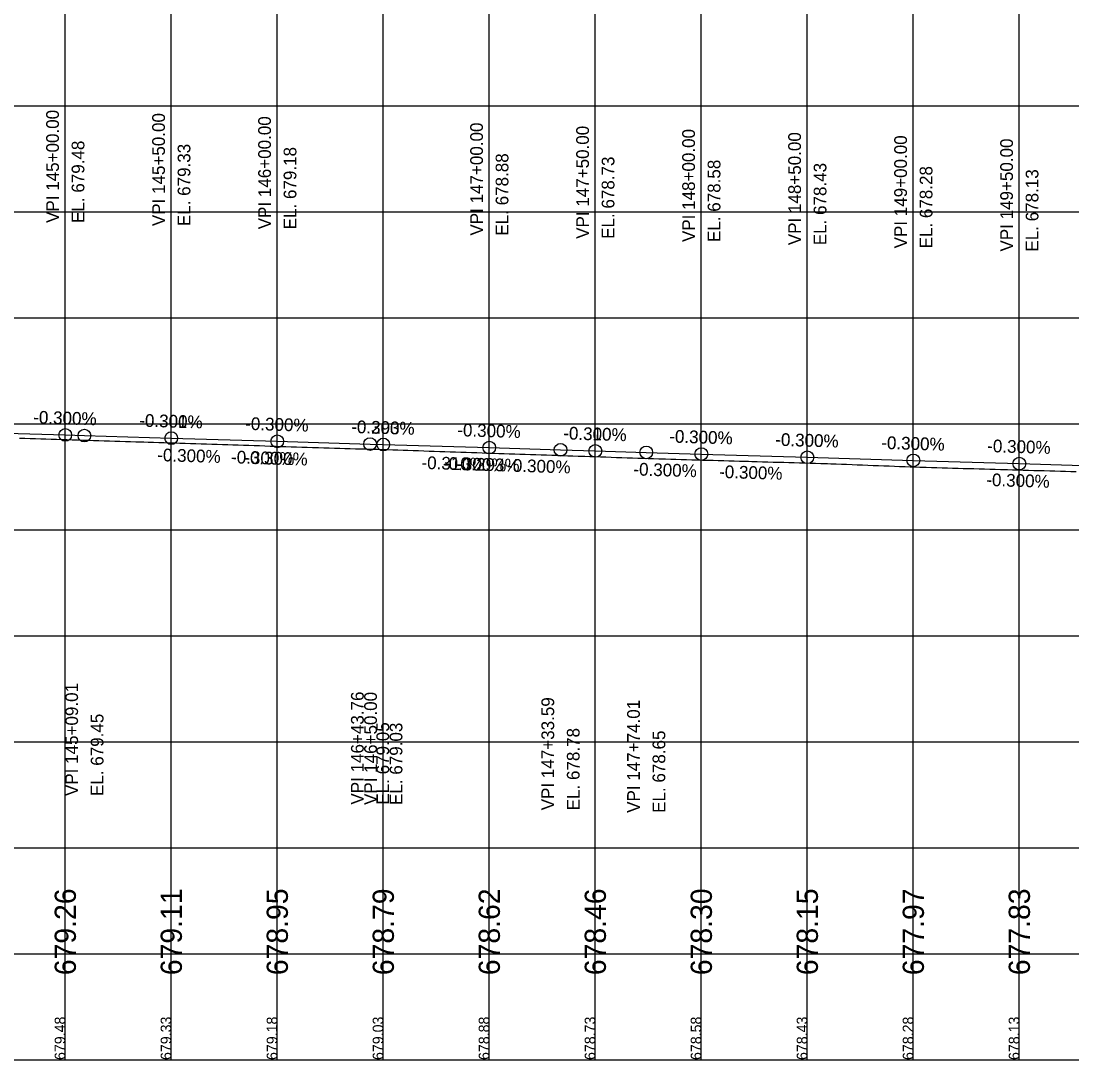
# Model space of a CAD drawing. Extents: x -7164 to 2214450, y -19642 to 253469.
# Drawn here: x 21679.1 to 22174.8, y -3000 to -2510 of the extents above; entities that cross this region are included whole.
import ezdxf

# ---------------------------------------------------------------- set-up
doc = ezdxf.new("R2010")
doc.units = 0
for name, color, linetype in [('DESIGN - PROFILE - Proposed', 7, 'Continuous'), ('DESIGN - PROFILE - Proposed Curve Text', 7, 'Continuous'), ('DESIGN - PROFILE - Proposed Text', 7, 'Continuous'), ('DESIGN - SCRATCH - User 1', 7, 'Continuous'), ('DESIGN - SHEET - Light Grid', 7, 'Continuous'), ('SURVEY - PROFILE - Ground Line with Text', 7, 'Continuous')]:
    doc.layers.add(name, color=color, linetype=linetype)

msp = doc.modelspace()

# ---------------------------------------------------------------- linework, layer by layer
at = {"layer": 'DESIGN - PROFILE - Proposed'}
msp.add_lwpolyline([(21650, -2703.73), (21700, -2705.23), (21709.01, -2705.51), (21750, -2706.73), (21800, -2708.23), (21843.76, -2709.55), (21850, -2709.73), (21900, -2711.2), (21933.59, -2712.24), (21950, -2712.73), (21974.01, -2713.45), (22000, -2714.23), (22050, -2715.73), (22100, -2717.23), (22150, -2718.73), (22200, -2720.23)], dxfattribs=at)
msp.add_lwpolyline([(21650, -2703.73), (21700, -2705.23), (21709.01, -2705.51), (21750, -2706.73), (21800, -2708.23), (21843.76, -2709.55), (21850, -2709.73), (21900, -2711.2), (21933.59, -2712.24), (21950, -2712.73), (21974.01, -2713.45), (22000, -2714.23), (22050, -2715.73), (22100, -2717.23), (22150, -2718.73), (22200, -2720.23)], dxfattribs=at)
at = {"layer": 'DESIGN - PROFILE - Proposed Text'}
for centre in [(21700, -2705.23), (21700, -2705.23), (21709.01, -2705.51), (21709.01, -2705.51), (21750, -2706.73), (21750, -2706.73), (21800, -2708.23), (21800, -2708.23), (21843.76, -2709.55), (21843.76, -2709.55), (21850, -2709.73), (21850, -2709.73), (21900, -2711.2), (21900, -2711.2), (21933.59, -2712.24), (21933.59, -2712.24), (21950, -2712.73), (21950, -2712.73), (21974.01, -2713.45), (21974.01, -2713.45), (22000, -2714.23), (22000, -2714.23), (22050, -2715.73), (22050, -2715.73), (22100, -2717.23), (22100, -2717.23), (22150, -2718.73), (22150, -2718.73)]:
    msp.add_circle(centre, 3, dxfattribs=at)
at = {"layer": 'DESIGN - SCRATCH - User 1'}
msp.add_line((15000, -3000), (24100, -3000), dxfattribs=at)
msp.add_line((15000, -3000), (24100, -3000), dxfattribs=at)
at = {"layer": 'DESIGN - SHEET - Light Grid'}
for p, q in [((21700, -3000), (21700, -1000)), ((21700, -3000), (21700, -1000)), ((21750, -3000), (21750, -1000)), ((21750, -3000), (21750, -1000)), ((21800, -3000), (21800, -1000)), ((21800, -3000), (21800, -1000)), ((21850, -3000), (21850, -1000)), ((21850, -3000), (21850, -1000)), ((21900, -3000), (21900, -1000)), ((21900, -3000), (21900, -1000)), ((21950, -3000), (21950, -1000)), ((21950, -3000), (21950, -1000)), ((22000, -3000), (22000, -1000)), ((22000, -3000), (22000, -1000)), ((22050, -3000), (22050, -1000)), ((22050, -3000), (22050, -1000)), ((22100, -3000), (22100, -1000)), ((22100, -3000), (22100, -1000)), ((22150, -3000), (22150, -1000)), ((22150, -3000), (22150, -1000)), ((15000, -2550), (24100, -2550)), ((15000, -2550), (24100, -2550)), ((15000, -2600), (24100, -2600)), ((15000, -2600), (24100, -2600)), ((15000, -2650), (24100, -2650)), ((15000, -2650), (24100, -2650)), ((15000, -2700), (24100, -2700)), ((15000, -2700), (24100, -2700)), ((15000, -2750), (24100, -2750)), ((15000, -2750), (24100, -2750)), ((15000, -2800), (24100, -2800)), ((15000, -2800), (24100, -2800)), ((15000, -2850), (24100, -2850)), ((15000, -2850), (24100, -2850)), ((15000, -2900), (24100, -2900)), ((15000, -2900), (24100, -2900)), ((15000, -2950), (24100, -2950)), ((15000, -2950), (24100, -2950)), ((15000, -3000), (24100, -3000)), ((15000, -3000), (24100, -3000))]:
    msp.add_line(p, q, dxfattribs=at)
at = {"layer": 'SURVEY - PROFILE - Ground Line with Text'}
for points in [[(21678.38, -2706.7), (21680.89, -2706.77), (21683.38, -2706.85), (21685.88, -2706.93)], [(21678.38, -2706.7), (21680.89, -2706.77), (21683.38, -2706.85), (21685.88, -2706.93)], [(21685.88, -2706.93), (21688.39, -2707.01), (21690.88, -2707.08), (21693.39, -2707.17), (21695.88, -2707.24), (21698.39, -2707.32), (21700.8, -2707.39), (21703.31, -2707.48), (21705.8, -2707.55), (21708.32, -2707.63), (21710.79, -2707.7), (21713.32, -2707.79), (21715.79, -2707.86), (21718.32, -2707.94), (21720.79, -2708.01), (21723.33, -2708.1), (21725.79, -2708.17), (21728.33, -2708.25), (21730.79, -2708.32), (21733.34, -2708.41), (21735.79, -2708.48), (21737.08, -2708.52), (21739.07, -2708.59), (21741.62, -2708.67), (21744.08, -2708.75), (21746.62, -2708.83), (21749.08, -2708.91), (21751.62, -2708.99), (21754.08, -2709.07), (21756.62, -2709.15), (21759.08, -2709.23), (21761.62, -2709.31), (21764.08, -2709.39), (21766.62, -2709.47), (21769.08, -2709.55), (21771.61, -2709.63), (21774.09, -2709.71), (21776.61, -2709.79), (21779.09, -2709.87), (21781.61, -2709.95), (21784.09, -2710.03), (21786.61, -2710.11), (21789.09, -2710.19), (21791.61, -2710.27), (21794.09, -2710.35), (21796.61, -2710.44), (21799.1, -2710.52), (21801.61, -2710.6), (21804.1, -2710.68), (21806.61, -2710.76), (21809.1, -2710.84), (21811.6, -2710.92), (21814.1, -2711), (21816.6, -2711.08), (21816.92, -2711.09), (21819.42, -2711.17), (21821.92, -2711.24), (21824.43, -2711.32), (21826.92, -2711.39), (21829.43, -2711.47), (21831.91, -2711.54), (21834.43, -2711.62), (21836.91, -2711.69), (21839.44, -2711.77), (21841.52, -2711.83), (21841.91, -2711.84), (21844.44, -2711.92), (21846.9, -2711.99), (21849.44, -2712.07), (21851.9, -2712.14), (21854.44, -2712.23), (21856.9, -2712.3), (21859.44, -2712.38), (21860.79, -2712.42), (21861.6, -2712.45), (21864.05, -2712.53), (21866.6, -2712.62), (21869.05, -2712.7), (21871.6, -2712.79), (21874.04, -2712.87), (21876.6, -2712.96), (21879.04, -2713.04), (21881.6, -2713.14), (21884.04, -2713.22), (21886.6, -2713.31), (21889.04, -2713.39), (21891.6, -2713.48), (21894.04, -2713.56), (21896.6, -2713.66), (21899.05, -2713.74), (21901.6, -2713.83), (21901.64, -2713.84), (21901.98, -2713.85), (21904.43, -2713.93), (21906.98, -2714.01), (21909.43, -2714.1), (21911.98, -2714.17), (21914.43, -2714.26), (21916.98, -2714.34), (21919.43, -2714.42), (21921.98, -2714.5)], [(21685.88, -2706.93), (21688.39, -2707.01), (21690.88, -2707.08), (21693.39, -2707.17), (21695.88, -2707.24), (21698.39, -2707.32), (21700.8, -2707.39), (21703.31, -2707.48), (21705.8, -2707.55), (21708.32, -2707.63), (21710.79, -2707.7), (21713.32, -2707.79), (21715.79, -2707.86), (21718.32, -2707.94), (21720.79, -2708.01), (21723.33, -2708.1), (21725.79, -2708.17), (21728.33, -2708.25), (21730.79, -2708.32), (21733.34, -2708.41), (21735.79, -2708.48), (21737.08, -2708.52), (21739.07, -2708.59), (21741.62, -2708.67), (21744.08, -2708.75), (21746.62, -2708.83), (21749.08, -2708.91), (21751.62, -2708.99), (21754.08, -2709.07), (21756.62, -2709.15), (21759.08, -2709.23), (21761.62, -2709.31), (21764.08, -2709.39), (21766.62, -2709.47), (21769.08, -2709.55), (21771.61, -2709.63), (21774.09, -2709.71), (21776.61, -2709.79), (21779.09, -2709.87), (21781.61, -2709.95), (21784.09, -2710.03), (21786.61, -2710.11), (21789.09, -2710.19), (21791.61, -2710.27), (21794.09, -2710.35), (21796.61, -2710.44), (21799.1, -2710.52), (21801.61, -2710.6), (21804.1, -2710.68), (21806.61, -2710.76), (21809.1, -2710.84), (21811.6, -2710.92), (21814.1, -2711), (21816.6, -2711.08), (21816.92, -2711.09), (21819.42, -2711.17), (21821.92, -2711.24), (21824.43, -2711.32), (21826.92, -2711.39), (21829.43, -2711.47), (21831.91, -2711.54), (21834.43, -2711.62), (21836.91, -2711.69), (21839.44, -2711.77), (21841.52, -2711.83), (21841.91, -2711.84), (21844.44, -2711.92), (21846.9, -2711.99), (21849.44, -2712.07), (21851.9, -2712.14), (21854.44, -2712.23), (21856.9, -2712.3), (21859.44, -2712.38), (21860.79, -2712.42), (21861.6, -2712.45), (21864.05, -2712.53), (21866.6, -2712.62), (21869.05, -2712.7), (21871.6, -2712.79), (21874.04, -2712.87), (21876.6, -2712.96), (21879.04, -2713.04), (21881.6, -2713.14), (21884.04, -2713.22), (21886.6, -2713.31), (21889.04, -2713.39), (21891.6, -2713.48), (21894.04, -2713.56), (21896.6, -2713.66), (21899.05, -2713.74), (21901.6, -2713.83), (21901.64, -2713.84), (21901.98, -2713.85), (21904.43, -2713.93), (21906.98, -2714.01), (21909.43, -2714.1), (21911.98, -2714.17), (21914.43, -2714.26), (21916.98, -2714.34), (21919.43, -2714.42), (21921.98, -2714.5)], [(21921.98, -2714.5), (21924.43, -2714.59), (21926.98, -2714.67), (21929.44, -2714.76), (21931.98, -2714.83), (21934.44, -2714.92), (21936.98, -2715), (21939.45, -2715.09), (21941.97, -2715.17), (21943.76, -2715.23), (21945.01, -2715.27), (21947.48, -2715.36), (21950.01, -2715.44), (21952.48, -2715.52), (21955.01, -2715.61), (21957.47, -2715.69), (21960.01, -2715.78), (21962.48, -2715.86), (21965.01, -2715.95), (21967.48, -2716.03), (21970.01, -2716.12), (21972.48, -2716.21), (21975.01, -2716.29), (21977.49, -2716.38), (21980.01, -2716.46), (21980.58, -2716.48), (21983.03, -2716.55), (21985.55, -2716.62), (21988.03, -2716.69), (21990.55, -2716.75), (21993.02, -2716.83), (21995.55, -2716.9), (21998.02, -2716.97), (22000.55, -2717.04), (22003.02, -2717.11), (22005.55, -2717.18), (22008.02, -2717.26), (22010.55, -2717.32), (22013.03, -2717.4), (22015.55, -2717.47), (22018.03, -2717.54), (22020.55, -2717.61), (22022.24, -2717.66), (22023.86, -2717.7), (22026.34, -2717.78), (22028.87, -2717.84), (22031.34, -2717.92), (22033.87, -2717.99), (22036.33, -2718.06), (22038.87, -2718.13), (22041.33, -2718.2), (22043.87, -2718.27), (22046.33, -2718.35), (22048.87, -2718.42), (22051.33, -2718.49), (22053.87, -2718.56), (22056.34, -2718.64), (22058.87, -2718.71), (22059.49, -2718.73), (22061.07, -2718.79), (22063.54, -2718.89), (22066.08, -2718.98), (22068.54, -2719.07), (22071.08, -2719.17), (22073.54, -2719.26), (22076.08, -2719.36), (22078.54, -2719.45), (22081.08, -2719.55), (22083.54, -2719.64), (22086.08, -2719.74), (22088.54, -2719.83), (22091.08, -2719.93), (22093.54, -2720.03), (22096.08, -2720.12), (22098.54, -2720.22), (22101.07, -2720.31), (22103.05, -2720.36), (22103.56, -2720.38), (22106.1, -2720.46), (22108.56, -2720.52), (22111.11, -2720.61), (22113.55, -2720.67), (22116.12, -2720.76), (22118.55, -2720.82), (22121.12, -2720.91), (22123.55, -2720.97), (22126.13, -2721.06), (22128.55, -2721.12), (22131.13, -2721.21), (22133.55, -2721.27), (22136.13, -2721.36), (22138.55, -2721.42), (22141.13, -2721.51), (22143.55, -2721.57), (22144.36, -2721.59), (22146.78, -2721.65), (22149.36, -2721.73), (22151.78, -2721.79), (22154.36, -2721.86), (22156.78, -2721.93), (22159.36, -2722)], [(21921.98, -2714.5), (21924.43, -2714.59), (21926.98, -2714.67), (21929.44, -2714.76), (21931.98, -2714.83), (21934.44, -2714.92), (21936.98, -2715), (21939.45, -2715.09), (21941.97, -2715.17), (21943.76, -2715.23), (21945.01, -2715.27), (21947.48, -2715.36), (21950.01, -2715.44), (21952.48, -2715.52), (21955.01, -2715.61), (21957.47, -2715.69), (21960.01, -2715.78), (21962.48, -2715.86), (21965.01, -2715.95), (21967.48, -2716.03), (21970.01, -2716.12), (21972.48, -2716.21), (21975.01, -2716.29), (21977.49, -2716.38), (21980.01, -2716.46), (21980.58, -2716.48), (21983.03, -2716.55), (21985.55, -2716.62), (21988.03, -2716.69), (21990.55, -2716.75), (21993.02, -2716.83), (21995.55, -2716.9), (21998.02, -2716.97), (22000.55, -2717.04), (22003.02, -2717.11), (22005.55, -2717.18), (22008.02, -2717.26), (22010.55, -2717.32), (22013.03, -2717.4), (22015.55, -2717.47), (22018.03, -2717.54), (22020.55, -2717.61), (22022.24, -2717.66), (22023.86, -2717.7), (22026.34, -2717.78), (22028.87, -2717.84), (22031.34, -2717.92), (22033.87, -2717.99), (22036.33, -2718.06), (22038.87, -2718.13), (22041.33, -2718.2), (22043.87, -2718.27), (22046.33, -2718.35), (22048.87, -2718.42), (22051.33, -2718.49), (22053.87, -2718.56), (22056.34, -2718.64), (22058.87, -2718.71), (22059.49, -2718.73), (22061.07, -2718.79), (22063.54, -2718.89), (22066.08, -2718.98), (22068.54, -2719.07), (22071.08, -2719.17), (22073.54, -2719.26), (22076.08, -2719.36), (22078.54, -2719.45), (22081.08, -2719.55), (22083.54, -2719.64), (22086.08, -2719.74), (22088.54, -2719.83), (22091.08, -2719.93), (22093.54, -2720.03), (22096.08, -2720.12), (22098.54, -2720.22), (22101.07, -2720.31), (22103.05, -2720.36), (22103.56, -2720.38), (22106.1, -2720.46), (22108.56, -2720.52), (22111.11, -2720.61), (22113.55, -2720.67), (22116.12, -2720.76), (22118.55, -2720.82), (22121.12, -2720.91), (22123.55, -2720.97), (22126.13, -2721.06), (22128.55, -2721.12), (22131.13, -2721.21), (22133.55, -2721.27), (22136.13, -2721.36), (22138.55, -2721.42), (22141.13, -2721.51), (22143.55, -2721.57), (22144.36, -2721.59), (22146.78, -2721.65), (22149.36, -2721.73), (22151.78, -2721.79), (22154.36, -2721.86), (22156.78, -2721.93), (22159.36, -2722)], [(22159.36, -2722), (22161.79, -2722.06), (22164.36, -2722.14), (22166.79, -2722.2), (22169.35, -2722.27), (22171.8, -2722.34), (22174.35, -2722.41), (22176.8, -2722.48)], [(22159.36, -2722), (22161.79, -2722.06), (22164.36, -2722.14), (22166.79, -2722.2), (22169.35, -2722.27), (22171.8, -2722.34), (22174.35, -2722.41), (22176.8, -2722.48)]]:
    msp.add_lwpolyline(points, dxfattribs=at)

# ---------------------------------------------------------------- texts
at = {"layer": 'DESIGN - PROFILE - Proposed Curve Text'}
for s, p in [('VPI 145+00.00', (21697, -2605.23)), ('VPI 145+00.00', (21697, -2605.23)), ('VPI 145+50.00', (21747, -2606.73)), ('VPI 145+50.00', (21747, -2606.73)), ('VPI 146+00.00', (21797, -2608.23)), ('VPI 146+00.00', (21797, -2608.23)), ('VPI 147+00.00', (21897, -2611.2)), ('VPI 147+00.00', (21897, -2611.2)), ('VPI 147+50.00', (21947, -2612.73)), ('VPI 147+50.00', (21947, -2612.73)), ('VPI 148+00.00', (21997, -2614.23)), ('VPI 148+00.00', (21997, -2614.23)), ('VPI 148+50.00', (22047, -2615.73)), ('VPI 148+50.00', (22047, -2615.73)), ('EL. 679.48', (21709, -2605.23)), ('EL. 679.48', (21709, -2605.23)), ('VPI 149+00.00', (22097, -2617.23)), ('VPI 149+00.00', (22097, -2617.23)), ('VPI 149+50.00', (22147, -2618.73)), ('VPI 149+50.00', (22147, -2618.73)), ('EL. 679.33', (21759, -2606.73)), ('EL. 679.33', (21759, -2606.73)), ('EL. 679.18', (21809, -2608.23)), ('EL. 679.18', (21809, -2608.23)), ('EL. 678.88', (21909, -2611.2)), ('EL. 678.88', (21909, -2611.2)), ('EL. 678.73', (21959, -2612.73)), ('EL. 678.73', (21959, -2612.73)), ('EL. 678.58', (22009, -2614.23)), ('EL. 678.58', (22009, -2614.23)), ('EL. 678.43', (22059, -2615.73)), ('EL. 678.43', (22059, -2615.73)), ('EL. 678.28', (22109, -2617.23)), ('EL. 678.28', (22109, -2617.23)), ('EL. 678.13', (22159, -2618.73)), ('EL. 678.13', (22159, -2618.73)), ('VPI 145+09.01', (21706.01, -2875.51)), ('VPI 145+09.01', (21706.01, -2875.51)), ('VPI 146+43.76', (21840.76, -2879.55)), ('VPI 146+43.76', (21840.76, -2879.55)), ('VPI 146+50.00', (21847, -2879.73)), ('VPI 146+50.00', (21847, -2879.73)), ('VPI 147+33.59', (21930.59, -2882.24)), ('VPI 147+33.59', (21930.59, -2882.24)), ('VPI 147+74.01', (21971.01, -2883.45)), ('VPI 147+74.01', (21971.01, -2883.45)), ('EL. 679.45', (21718.01, -2875.51)), ('EL. 679.45', (21718.01, -2875.51)), ('EL. 679.05', (21852.76, -2879.55)), ('EL. 679.05', (21852.76, -2879.55)), ('EL. 679.03', (21859, -2879.73)), ('EL. 679.03', (21859, -2879.73)), ('EL. 678.78', (21942.59, -2882.24)), ('EL. 678.78', (21942.59, -2882.24)), ('EL. 678.65', (21983.01, -2883.45)), ('EL. 678.65', (21983.01, -2883.45))]:
    msp.add_text(s, height=6, rotation=90, dxfattribs=at).set_placement(p)
at = {"layer": 'DESIGN - PROFILE - Proposed Text'}
for s, height, rotation, p in [('-0.300%', 6, 358.2816, (21684.79, -2699.78)), ('-0.300%', 6, 358.2816, (21684.79, -2699.78)), ('-0.300%', 6, 358.2826, (21684.84, -2699.78)), ('-0.300%', 6, 358.2826, (21684.84, -2699.78)), ('-0.301%', 6, 358.2772, (21734.79, -2701.28)), ('-0.301%', 6, 358.2772, (21734.79, -2701.28)), ('-0.300%', 6, 358.2816, (21734.84, -2701.28)), ('-0.300%', 6, 358.2816, (21734.84, -2701.28)), ('-0.300%', 6, 358.2816, (21784.79, -2702.78)), ('-0.300%', 6, 358.2816, (21784.79, -2702.78)), ('-0.300%', 6, 358.2814, (21834.79, -2704.28)), ('-0.300%', 6, 358.2814, (21834.79, -2704.28)), ('-0.293%', 6, 358.3206, (21834.83, -2704.29)), ('-0.293%', 6, 358.3206, (21834.83, -2704.29)), ('-0.300%', 6, 358.2827, (21884.84, -2705.78)), ('-0.300%', 6, 358.2827, (21884.84, -2705.78)), ('-0.310%', 6, 358.2232, (21934.8, -2707.28)), ('-0.310%', 6, 358.2232, (21934.8, -2707.28)), ('-0.300%', 6, 358.2832, (21934.84, -2707.28)), ('-0.300%', 6, 358.2832, (21934.84, -2707.28)), ('-0.300%', 6, 358.28, (21984.79, -2708.78)), ('-0.300%', 6, 358.28, (21984.79, -2708.78)), ('-0.300%', 6, 358.2816, (21984.84, -2708.78)), ('-0.300%', 6, 358.2816, (21984.84, -2708.78)), ('-0.300%', 6, 358.2816, (22034.79, -2710.28)), ('-0.300%', 6, 358.2816, (22034.79, -2710.28)), ('-0.300%', 6, 358.2816, (22034.84, -2710.28)), ('-0.300%', 6, 358.2816, (22034.84, -2710.28)), ('-0.300%', 6, 358.2816, (22084.79, -2711.78)), ('-0.300%', 6, 358.2816, (22084.79, -2711.78)), ('-0.300%', 6, 358.2816, (22084.84, -2711.78)), ('-0.300%', 6, 358.2816, (22084.84, -2711.78)), ('-0.300%', 6, 358.2816, (22134.79, -2713.28)), ('-0.300%', 6, 358.2816, (22134.79, -2713.28)), ('-0.300%', 6, 358.2826, (21743.32, -2717.54)), ('-0.300%', 6, 358.2826, (21743.32, -2717.54)), ('-0.300%', 6, 358.2814, (21778.12, -2718.58)), ('-0.300%', 6, 358.2814, (21778.12, -2718.58)), ('-0.300%', 6, 358.2835, (21784.36, -2718.77)), ('-0.300%', 6, 358.2835, (21784.36, -2718.77)), ('-0.310%', 6, 358.2232, (21867.94, -2721.21)), ('-0.310%', 6, 358.2232, (21867.94, -2721.21)), ('-0.300%', 6, 358.2835, (21878.07, -2721.58)), ('-0.300%', 6, 358.2835, (21878.07, -2721.58)), ('-0.293%', 6, 358.3206, (21884.32, -2721.74)), ('-0.293%', 6, 358.3206, (21884.32, -2721.74)), ('-0.300%', 6, 358.28, (21908.37, -2722.49)), ('-0.300%', 6, 358.28, (21908.37, -2722.49)), ('-0.300%', 6, 358.2827, (21967.9, -2724.28)), ('-0.300%', 6, 358.2827, (21967.9, -2724.28)), ('-0.300%', 6, 358.2832, (22008.32, -2725.49)), ('-0.300%', 6, 358.2832, (22008.32, -2725.49)), ('-0.300%', 6, 358.2816, (22134.36, -2729.27)), ('-0.300%', 6, 358.2816, (22134.36, -2729.27)), ('679.48', 5, 90, (21700, -3000)), ('679.48', 5, 90, (21700, -3000)), ('679.33', 5, 90, (21750, -3000)), ('679.33', 5, 90, (21750, -3000)), ('679.18', 5, 90, (21800, -3000)), ('679.18', 5, 90, (21800, -3000)), ('679.03', 5, 90, (21850, -3000)), ('679.03', 5, 90, (21850, -3000)), ('678.88', 5, 90, (21900, -3000)), ('678.88', 5, 90, (21900, -3000)), ('678.73', 5, 90, (21950, -3000)), ('678.73', 5, 90, (21950, -3000)), ('678.58', 5, 90, (22000, -3000)), ('678.58', 5, 90, (22000, -3000)), ('678.43', 5, 90, (22050, -3000)), ('678.43', 5, 90, (22050, -3000)), ('678.28', 5, 90, (22100, -3000)), ('678.28', 5, 90, (22100, -3000)), ('678.13', 5, 90, (22150, -3000)), ('678.13', 5, 90, (22150, -3000))]:
    msp.add_text(s, height=height, rotation=rotation, dxfattribs=at).set_placement(p)
at = {"layer": 'SURVEY - PROFILE - Ground Line with Text'}
for s, p in [('679.26', (21705, -2960)), ('679.26', (21705, -2960)), ('678.95', (21805, -2960)), ('678.95', (21805, -2960)), ('678.79', (21855, -2960)), ('678.79', (21855, -2960)), ('678.46', (21955, -2960)), ('678.46', (21955, -2960)), ('678.30', (22005, -2960)), ('678.30', (22005, -2960)), ('678.15', (22055, -2960)), ('678.15', (22055, -2960)), ('677.83', (22155, -2960)), ('677.83', (22155, -2960)), ('679.11', (21755, -2960)), ('679.11', (21755, -2960)), ('678.62', (21905, -2960)), ('678.62', (21905, -2960)), ('677.97', (22105, -2960)), ('677.97', (22105, -2960))]:
    msp.add_text(s, height=10, rotation=90, dxfattribs=at).set_placement(p)

doc.saveas('drawing.dxf')
